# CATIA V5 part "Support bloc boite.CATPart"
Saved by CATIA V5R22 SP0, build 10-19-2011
Part number: Support bloc boite
Bounding box of the stored display mesh (mm): x -140 to 140, y -350 to 290, z 0 to 5
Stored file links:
  D:\PER\CAO_PER_MODIF_2025\CAO_PER_pick&place_2024P\Sous_Ensemble_Boite\Support bloc boite.CATPart
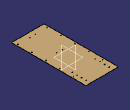
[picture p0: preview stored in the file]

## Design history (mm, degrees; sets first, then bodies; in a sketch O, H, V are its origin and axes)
Body1 (main body)
  Sketch1 on xy-plane, origin (0, 0, 0), H (1, 0, 0), V (0, 1, 0)
    line L1 (140, 350) -> (140, -350)
    line L2 (140, -350) -> (-140, -350)
    line L3 (-140, -350) -> (-140, 350)
    line L4 (-140, 350) -> (140, 350)
    length L1 = 700
    length L4 = 280
    vertical: L1 V, L3 V
    horizontal: L2 H, L4 H
    equidistance: L1 L3 O, L2 L4 O
  Pad1: profile Sketch1, direction (0, 0, 1), length 5
  Sketch2 on end face of Pad1, origin (0, 0, 5), H (1, 0, 0), V (0, 1, 0)
    projected line E1 (140, 350) -> (-140, 350) from edge [face of Pad1 from Sketch1.L4 | end face of Pad1]
    line L1 (140, 350) -> (140, 290)
    line L2 (140, 290) -> (-140, 290)
    line L3 (-140, 290) -> (-140, 350)
    distance L2 E1 = 60
    vertical: L1 V, L3 V
    horizontal: L2 H
  Pocket1: profile Sketch2, direction (0, 0, -1), through (limit type 3)
  DatumCurve1 to DatumCurve12
  Sketch3 on end face of Pad1, origin (0, 0, 5), H (1, 0, 0), V (0, 1, 0)
    projected circle E1 centre (99, 132.4085) radius 3.25 from edge of DatumCurve1
    projected circle E2 centre (99, 172.4085) radius 3.25 from edge of DatumCurve2
    projected circle E3 centre (99, 212.4085) radius 3.25 from edge of DatumCurve3
    projected circle E4 centre (99, 252.4085) radius 3.25 from edge of DatumCurve4
    projected circle E5 centre (-99, 252.4085) radius 3.25 from edge of DatumCurve5
    projected circle E6 centre (-99, 212.4085) radius 3.25 from edge of DatumCurve6
    projected circle E7 centre (-99, 172.4085) radius 3.25 from edge of DatumCurve7
    projected circle E8 centre (-99, 132.4085) radius 3.25 from edge of DatumCurve8
    projected circle E9 centre (22.5, -77.9975) radius 2.5 from edge of DatumCurve9
    projected circle E10 centre (-24.5, -77.9975) radius 2.5 from edge of DatumCurve10
    projected circle E11 centre (23, -308.9975) radius 2.5 from edge of DatumCurve11
    projected circle E12 centre (-24, -308.9975) radius 2.5 from edge of DatumCurve12
  Pocket2: profile Sketch3, direction (0, 0, -1), through (limit type 3)
  Chamfer1: length 4, angle 45, on edge [face of Pocket2 from Sketch3.E5 | start face of Pad1]; edge [face of Pocket2 from Sketch3.E6 | start face of Pad1]; edge [face of Pocket2 from Sketch3.E7 | start face of Pad1]; start face of Pad1; edge [face of Pocket2 from Sketch3.E4 | start face of Pad1]; edge [face of Pocket2 from Sketch3.E3 | start face of Pad1]; edge [face of Pocket2 from Sketch3.E2 | start face of Pad1]; edge [face of Pocket2 from Sketch3.E1 | start face of Pad1]
  Sketch4 on end face of Pad1, origin (0, 0, 5), H (1, 0, 0), V (0, 1, 0)
    circle A1 centre (125, -310) radius 3.5
    point P1 (125, -310)
    reference projected line E1 (-140, -350) -> (140, -350) from edge [face of Pad1 from Sketch1.L2 | end face of Pad1]
    reference projected line E2 (140, -350) -> (140, 350) from edge [face of Pad1 from Sketch1.L1 | end face of Pad1]
    reference intersected line E3 through (0, 0) direction (0, 1) from yz-plane
    circle A2 centre (-125, -310) radius 3.5
    distance P1 E1 = 40
    radius A1 = 3.5
    distance E2 P1 = 15
    symmetry: A1 A2 E3
  Pocket3: profile Sketch4, direction (0, 0, -1), through (limit type 3)
  RectPattern1: of Pocket3, direction 1 instances 5, spacing 120, along edge [face of Pad1 from Sketch1.L1 | end face of Pad1]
